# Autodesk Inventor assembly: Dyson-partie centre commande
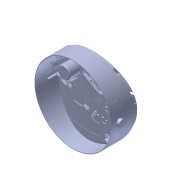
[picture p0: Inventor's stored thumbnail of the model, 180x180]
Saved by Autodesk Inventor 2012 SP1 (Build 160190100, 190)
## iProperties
Created: 2012-11
Part Number: Dyson-partie centre commande
Document SubType Name: Assembly
Designer: Administrateur
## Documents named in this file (7)
- D:\Cours\1-Cours-2013-14\Dropbox\1SI\1. Besoin\Dyson\Composants importés\Dyson Air Multiplier-Assemblage final\Dyson-partie centre commande.iam
- D:\Cours\1-Cours-2013-14\Dropbox\1SI\1. Besoin\Dyson\Composants importés\Dyson Air Multiplier-Assemblage final\Dyson-Partie centre commande.ipt
- D:\Cours\1-Cours-2013-14\Dropbox\1SI\1. Besoin\Dyson\Composants importés\Dyson Air Multiplier-Assemblage final\Dyson-Partie centre support commande.ipt
- D:\Cours\1-Cours-2013-14\Dropbox\1SI\1. Besoin\Dyson\Composants importés\Dyson Air Multiplier-Assemblage final\Vis torks M2x6.ipt
- D:\Cours\1-Cours-2013-14\Dropbox\1SI\1. Besoin\Dyson\Composants importés\Dyson Air Multiplier-Assemblage final\Dyson-Partie centre Ci commande.ipt
- D:\Cours\1-Cours-2013-14\Dropbox\1SI\1. Besoin\Dyson\Composants importés\Dyson Air Multiplier-Assemblage final\Dyson-Partie centre liaison.ipt
- D:\Cours\1-Cours-2013-14\Dropbox\1SI\1. Besoin\Dyson\Composants importés\Dyson Air Multiplier-Assemblage final\Dyson-partie centre motorisation.iam
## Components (10 placed, 6 different names)
1. Dyson-Partie centre commande:1
2. Dyson-Partie centre support commande:1
3. Vis torks M2x6:1
4. Vis torks M2x6:2
5. Dyson-Partie centre Ci commande:1
6. Vis torks M2x6:3
7. Vis torks M2x6:4
8. Vis torks M2x6:5
9. Dyson-Partie centre liaison:1
10. Dyson-partie centre motorisation:1 [sub-assembly]
